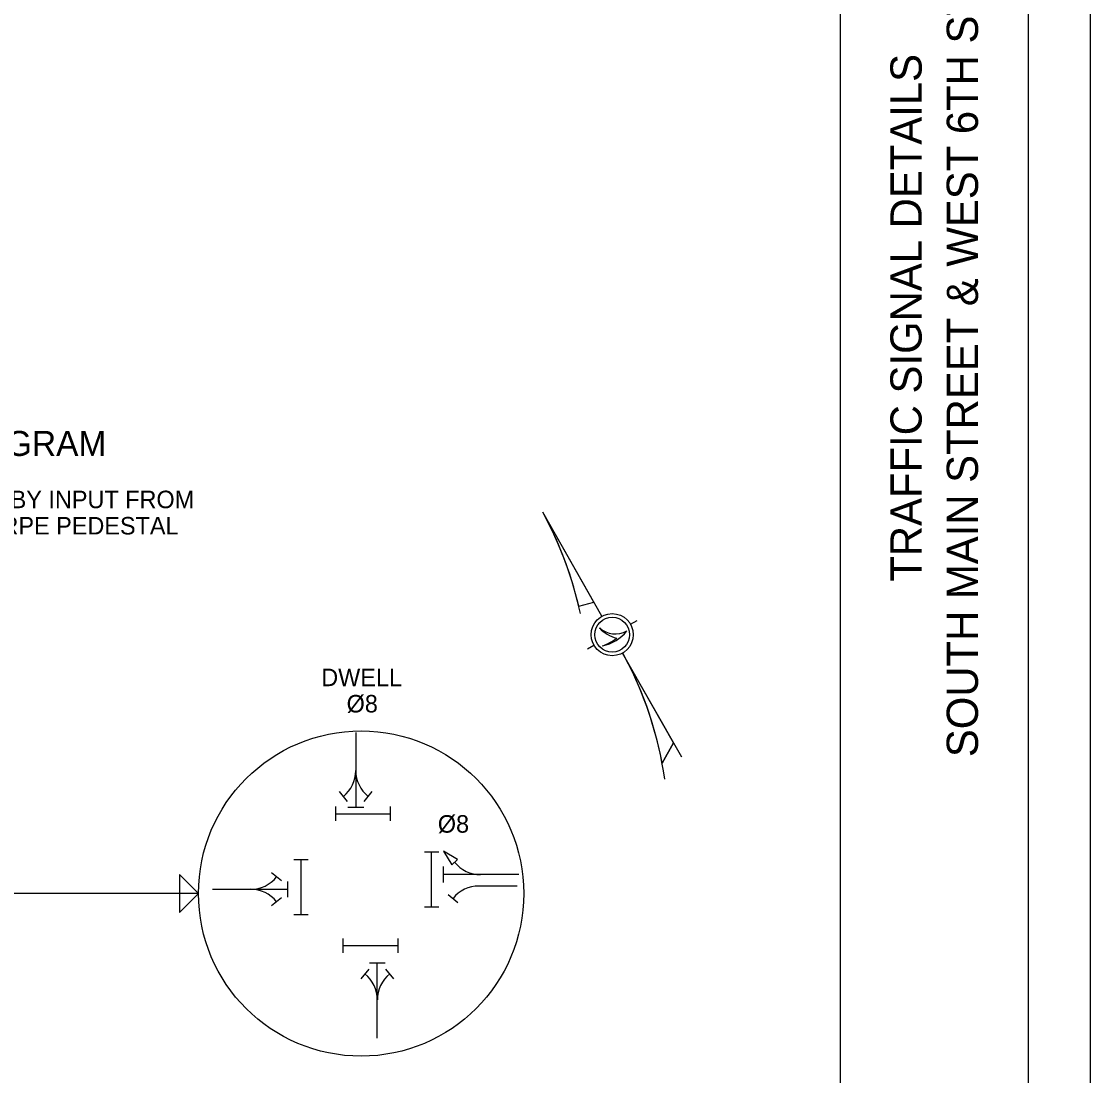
# Model space of a CAD drawing. Extents: x 0 to 680, y 0 to 551.
# Drawn here: x 509.1 to 680, y 141.9 to 310.4 of the extents above; entities that cross this region are included whole.
import ezdxf

# ---------------------------------------------------------------- set-up
doc = ezdxf.new("R2010")
doc.units = 0
for name, color, linetype in [('SG_P_Text', 7, 'Continuous'), ('SH_Border', 7, 'Continuous'), ('SH_Cut_Line', 7, 'Continuous'), ('SH_Data', 7, 'Continuous'), ('SH_Text', 7, 'Continuous')]:
    doc.layers.add(name, color=color, linetype=linetype)

msp = doc.modelspace()

# ---------------------------------------------------------------- linework, layer by layer
at = {"layer": 'SG_P_Text'}
for p, q in [((562.55, 196.77), (562.55, 190.66)), ((562.55, 196.77), (562.55, 190.66)), ((562.55, 196.77), (562.55, 184.75)), ((561.21, 185.73), (559.93, 187.32)), ((563.89, 185.73), (565.17, 187.32)), ((559.29, 184.92), (559.29, 182.64)), ((563.82, 184.75), (561.28, 184.75)), ((568.07, 184.92), (568.07, 182.64)), ((559.29, 183.78), (568.07, 183.78)), ((554.96, 176.41), (552.67, 176.41)), ((553.82, 167.63), (553.82, 176.41)), ((575.81, 177.64), (573.53, 177.64)), ((574.67, 168.86), (574.67, 177.64)), ((550.69, 173.04), (549.1, 174.32)), ((576.59, 172.78), (576.59, 175.32)), ((551.66, 172.97), (551.66, 170.43)), ((588.6, 174.05), (576.59, 174.05)), ((588.6, 174.05), (582.49, 174.05)), ((539.65, 171.7), (545.76, 171.7)), ((539.65, 171.7), (551.66, 171.7)), ((539.65, 171.7), (545.76, 171.7)), ((588.34, 172.22), (582.22, 172.22)), ((550.69, 170.36), (549.1, 169.08)), ((577.3, 170.88), (578.89, 169.59)), ((554.96, 167.63), (552.67, 167.63)), ((575.81, 168.86), (573.53, 168.86)), ((560.5, 163.84), (560.5, 161.56)), ((560.5, 162.7), (569.28, 162.7)), ((569.28, 163.84), (569.28, 161.56)), ((564.66, 158.96), (563.38, 157.37)), ((564.73, 159.94), (567.26, 159.94)), ((565.99, 147.93), (565.99, 159.94)), ((567.33, 158.96), (568.61, 157.37)), ((565.99, 147.93), (565.99, 154.04)), ((565.99, 147.93), (565.99, 154.04))]:
    msp.add_line(p, q, dxfattribs=at)
msp.add_lwpolyline([(578.8, 176.48), (576.59, 177.8), (577.91, 175.59)], close=True, dxfattribs=at)
msp.add_circle((563.41, 171.02), 25.99, dxfattribs=at)
for centre, start, end in [((557.25, 190.66), 308.7993, 0), ((567.85, 190.66), 180, 231.2007), ((582.49, 179.35), 218.7864, 269.9871), ((545.76, 177), 270, 321.2007), ((545.76, 166.4), 38.7993, 90), ((582.23, 166.92), 90.0129, 141.2136), ((560.69, 154.04), 360, 51.2007), ((571.3, 154.04), 128.7993, 180)]:
    msp.add_arc(centre, 5.3, start, end, dxfattribs=at)
at = {"layer": 'SH_Border'}
msp.add_line((640, 10), (640, 430), dxfattribs=at)
msp.add_lwpolyline([(30, 430), (670, 430), (670, 10), (30, 10)], close=True, dxfattribs=at)
at = {"layer": 'SH_Cut_Line'}
msp.add_lwpolyline([(0, 0), (680, 0), (680, 440), (0, 440)], close=True, dxfattribs=at)
at = {"layer": 'SH_Data'}
for p, q in [((601.88, 215.33), (592.43, 231.96)), ((598.2, 216.95), (600.61, 217.57)), ((606.48, 214.06), (607.52, 214.65)), ((599.57, 210.13), (600.61, 210.73)), ((614.65, 192.83), (605.21, 209.46)), ((613.36, 195.11), (611.51, 191.84)), ((537.42, 171.02), (501.79, 171.02))]:
    msp.add_line(p, q, dxfattribs=at)
for points in [[(598.19, 216.95), (598.2, 216.95), (600.61, 217.57), (592.43, 231.96)], [(611.51, 191.84), (613.36, 195.11), (605.21, 209.46)]]:
    msp.add_lwpolyline(points, dxfattribs=at)
msp.add_lwpolyline([(537.42, 171.02), (534.39, 174.06), (534.38, 167.99)], close=True, dxfattribs=at)
for radius in [3.37, 2.78]:
    msp.add_circle((603.54, 212.39), radius, dxfattribs=at)
for centre, radius, start, end in [((540.6, 203.48), 59.14, 12.006, 28.7854), ((540.6, 203.48), 59.14, 13.1661, 28.7854), ((604.02, 216.33), 3.82, 228.7482, 298.9617), ((605.47, 217.09), 5.38, 222.4464, 256.9049), ((600.59, 217.25), 6.79, 282.0781, 321.0767), ((599.04, 218.65), 8.57, 290.3184, 307.4642), ((553.38, 180.98), 59.14, 8.0961, 28.7854), ((553.38, 180.98), 59.14, 10.5844, 28.7854)]:
    msp.add_arc(centre, radius, start, end, dxfattribs=at)

# ---------------------------------------------------------------- texts
for s, p in [('SOUTH MAIN STREET & WEST 6TH STREET', (662, 192.82)), ('TRAFFIC SIGNAL DETAILS', (653, 220.85))]:
    msp.add_text(s, height=5, rotation=90, dxfattribs=at).set_placement(p)
at = {"layer": 'SH_Text'}
for s, height, p in [('PREEMPTION PHASING DIAGRAM', 4, (435.31, 240.95)), ('RRPE AT THIS SIGNAL SHALL BE INITIATED BY INPUT FROM', 2.8, (427.71, 232.6)), ('MAIN/6TH STREET NORFOLK SOUTHERN RRPE PEDESTAL', 2.8, (427.71, 228.4)), ('DWELL', 2.8, (557.04, 204.16)), ('Ø8', 2.8, (561.09, 199.96)), ('Ø8', 2.8, (575.67, 180.75))]:
    msp.add_text(s, height=height, dxfattribs=at).set_placement(p)

doc.saveas('drawing.dxf')
